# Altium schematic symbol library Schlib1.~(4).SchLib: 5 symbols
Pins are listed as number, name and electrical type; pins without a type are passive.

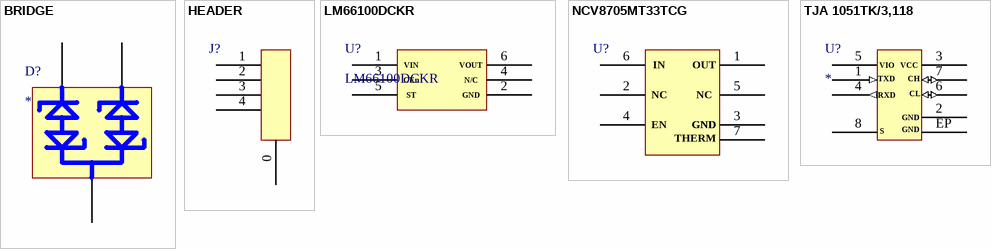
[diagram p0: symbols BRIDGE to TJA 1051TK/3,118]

## BRIDGE
designator D?
pins: 1, 2, 3

## HEADER
designator J?  (value not drawn)
pins: 0, 1, 2, 3, 4

## LM66100DCKR
designator U?
pins: 1, 2, 3, 4, 5, 6

## NCV8705MT33TCG
designator U?  (value not drawn)
pins: 1, 2, 3, 4, 5, 6, 7

## TJA 1051TK/3,118
designator U?
pins: 1 (in), 2, 3, 4 (out), 5, 6 (io), 7 (io), 8, EP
